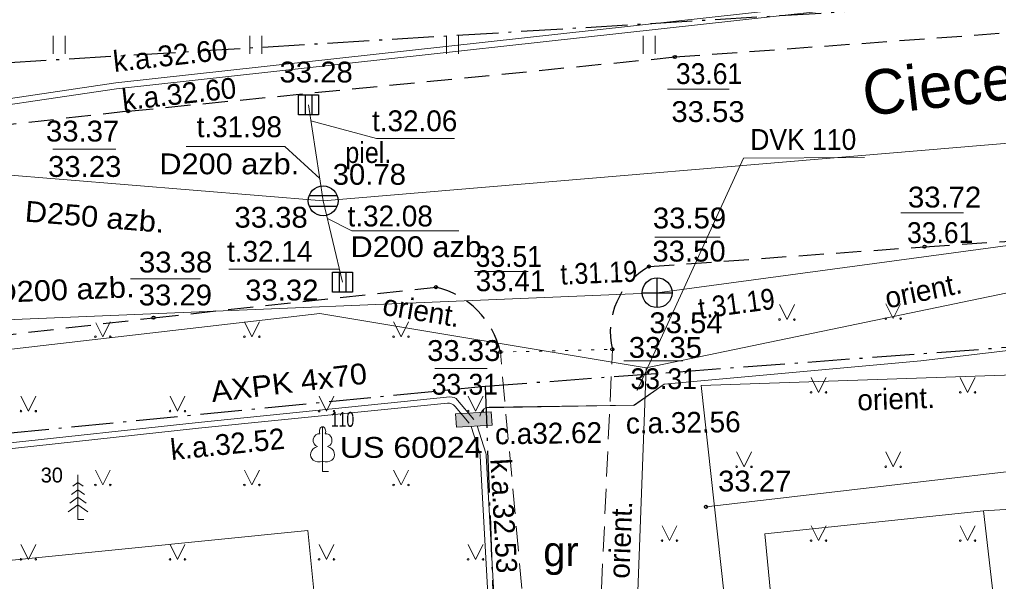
# Model space of a CAD drawing. Extents: x 380758 to 381729, y 283236 to 283533.
# Drawn here: x 381053.95 to 381086.8, y 283323.24 to 283342.11 of the extents above; entities that cross this region are included whole.
import ezdxf
from ezdxf.enums import TextEntityAlignment as Align

# ---------------------------------------------------------------- set-up
doc = ezdxf.new("R2010")
doc.units = 0
doc.header["$LTSCALE"] = 0.28
for name, pattern in [('DOT_DASHED', [7.7, 5, -1.2, 0.3, -1.2]), ('DOTTED', [1.5, 0.3, -1.2]), ('MEDIUM_DASHED', [4.5, 3, -1.5])]:
    doc.linetypes.add(name, pattern=pattern)
for name, color, linetype, lineweight in [('1', 7, 'Continuous', 13), ('11', 7, 'Continuous', 13), ('17', 7, 'Continuous', 13), ('18', 7, 'Continuous', 13), ('23', 7, 'Continuous', 13), ('29', 7, 'DOT_DASHED', 25), ('35', 7, 'Continuous', 13), ('37', 7, 'MEDIUM_DASHED', 13), ('38', 7, 'Continuous', 25), ('45', 7, 'Continuous', 13), ('47', 7, 'Continuous', 13), ('48', 7, 'Continuous', 25), ('58', 7, 'Continuous', 25), ('7', 7, 'Continuous', 13), ('9', 7, 'Continuous', 13)]:
    doc.layers.add(name, color=color, linetype=linetype, lineweight=lineweight)
doc.layers.add('56', color=7, linetype='Continuous')

msp = doc.modelspace()

# ---------------------------------------------------------------- hatches: boundary and pattern name
at = {"layer": '18'}
msp.add_hatch(color=256, dxfattribs=at).paths.add_polyline_path([(381068.581, 283328.865), (381069.779, 283328.94), (381069.807, 283328.491), (381068.609, 283328.416)])

# ---------------------------------------------------------------- linework, layer by layer
at = {"layer": '1'}
for p, q in [((381064.116, 283328.432), (381064.116, 283327.279)), ((381064.206, 283328.2), (381064.205, 283328.201)), ((381064.116, 283327.279), (381064.116, 283326.932)), ((381055.906, 283326.818), (381055.906, 283325.318)), ((381064.116, 283326.932), (381064.316, 283326.932)), ((381055.906, 283326.568), (381055.73, 283326.44)), ((381055.906, 283326.568), (381056.08, 283326.44)), ((381055.906, 283326.068), (381055.628, 283325.864)), ((381055.906, 283326.318), (381055.69, 283326.16)), ((381055.906, 283326.318), (381056.122, 283326.16)), ((381055.906, 283326.068), (381056.184, 283325.864)), ((381055.906, 283325.818), (381055.574, 283325.574)), ((381055.906, 283325.818), (381056.24, 283325.574)), ((381055.906, 283325.318), (381056.106, 283325.318))]:
    msp.add_line(p, q, dxfattribs=at)
msp.add_lwpolyline([(381076.989, 283325.745), (381094.84, 283327.827), (381097.154, 283316.912)], dxfattribs=at)
for centre, major_axis, ratio, start_param, end_param in [((381064.1164, 283328.2821), (0, -0.1499), 0.707107, 3.1453698, 5.2874846), ((381064.1156, 283328.2821), (0, -0.1499), 0.707107, 0.9957007, 3.1378155), ((381063.9877, 283327.9872), (-0.0387, -0.2124), 0.861323, 3.1415927, 6.2831853), ((381064.2443, 283327.9872), (0.0387, -0.2124), 0.861323, 6.2831853, 9.424778), ((381064.0264, 283327.5249), (0.3068, 0.0951), 0.814445, 1.5707963, 4.7520146), ((381064.2056, 283327.5249), (-0.3068, 0.0951), 0.814445, 1.5311707, 4.712389)]:
    msp.add_ellipse(centre, major_axis=major_axis, ratio=ratio, start_param=start_param, end_param=end_param, dxfattribs=at)
at = {"layer": '11'}
for p, q in [((381064.135, 283336.022), (381114.289, 283340.241)), ((381064.135, 283336.022), (381063.643, 283339.248)), ((381045.914, 283337.51), (381064.135, 283336.022)), ((381064.135, 283336.022), (381064.786, 283333.287)), ((381060.967, 283333.732), (381064.68, 283333.732))]:
    msp.add_line(p, q, dxfattribs=at)
for points in [[(381068.541, 283338.115), (381065.925, 283338.115), (381063.726, 283338.706)], [(381059.537, 283337.841), (381062.853, 283337.841), (381064.02, 283336.773)], [(381068.693, 283335.01), (381065.104, 283335.01), (381064.277, 283335.424)]]:
    msp.add_lwpolyline(points, dxfattribs=at)
at = {"layer": '17'}
for points in [[(381104.068, 283335.267), (381095.95, 283334.767), (381074.983, 283330.417), (381064.026, 283332.241)], [(381045.194, 283329.97), (381049.305, 283330.531), (381064.026, 283332.241)], [(381074.983, 283330.417), (381074.575, 283319.597), (381079.19, 283319.291), (381080.612, 283314.576)]]:
    msp.add_lwpolyline(points, dxfattribs=at)
at = {"layer": '18'}
msp.add_lwpolyline([(381068.581, 283328.865), (381069.779, 283328.94), (381069.807, 283328.491), (381068.609, 283328.416)], close=True, dxfattribs=at)
at = {"layer": '23'}
for p, q in [((381055.077, 283340.961), (381055.077, 283341.561)), ((381055.477, 283340.961), (381055.477, 283341.561)), ((381061.677, 283340.961), (381061.677, 283341.561)), ((381062.077, 283340.961), (381062.077, 283341.561)), ((381068.277, 283340.961), (381068.277, 283341.561)), ((381068.677, 283340.961), (381068.677, 283341.561)), ((381074.877, 283340.961), (381074.877, 283341.561)), ((381075.277, 283340.961), (381075.277, 283341.561))]:
    msp.add_line(p, q, dxfattribs=at)
for points in [[(381079.457, 283332.535), (381079.707, 283332.035), (381079.957, 283332.535)], [(381083.021, 283332.567), (381083.271, 283332.067), (381083.521, 283332.567)], [(381056.51, 283331.923), (381056.742, 283331.459), (381056.992, 283331.959)], [(381061.496, 283331.959), (381061.746, 283331.459), (381061.996, 283331.959)], [(381066.5, 283331.959), (381066.75, 283331.459), (381067, 283331.959)], [(381080.517, 283330.089), (381080.767, 283329.589), (381081.017, 283330.089)], [(381085.521, 283330.089), (381085.771, 283329.589), (381086.021, 283330.089)], [(381053.992, 283329.459), (381054.242, 283328.959), (381054.492, 283329.459)], [(381058.996, 283329.459), (381059.246, 283328.959), (381059.496, 283329.459)], [(381064, 283329.459), (381064.25, 283328.959), (381064.5, 283329.459)], [(381069.004, 283329.459), (381069.254, 283328.959), (381069.504, 283329.459)], [(381078.017, 283327.589), (381078.267, 283327.089), (381078.517, 283327.589)], [(381083.021, 283327.589), (381083.271, 283327.089), (381083.521, 283327.589)], [(381056.492, 283326.981), (381056.742, 283326.481), (381056.992, 283326.981)], [(381061.496, 283326.981), (381061.746, 283326.481), (381061.996, 283326.981)], [(381066.5, 283326.981), (381066.75, 283326.481), (381067, 283326.981)], [(381075.513, 283325.111), (381075.763, 283324.611), (381076.013, 283325.111)], [(381080.517, 283325.111), (381080.767, 283324.611), (381081.017, 283325.111)], [(381085.521, 283325.111), (381085.771, 283324.611), (381086.021, 283325.111)], [(381053.992, 283324.481), (381054.242, 283323.981), (381054.492, 283324.481)], [(381058.996, 283324.481), (381059.246, 283323.981), (381059.496, 283324.481)], [(381064, 283324.481), (381064.25, 283323.981), (381064.5, 283324.481)], [(381069.004, 283324.481), (381069.254, 283323.981), (381069.504, 283324.481)]]:
    msp.add_lwpolyline(points, dxfattribs=at)
for centre, radius in [((381079.4566, 283332.0342), 0.028), ((381079.9566, 283332.0342), 0.0263), ((381083.0206, 283332.0669), 0.028), ((381083.5206, 283332.0669), 0.0263), ((381056.4915, 283331.4581), 0.028), ((381056.9915, 283331.4581), 0.0263), ((381061.4955, 283331.4581), 0.028), ((381061.9955, 283331.4581), 0.0263), ((381066.4995, 283331.4581), 0.028), ((381066.9995, 283331.4581), 0.0263), ((381080.5166, 283329.5889), 0.028), ((381081.0166, 283329.5889), 0.0263), ((381085.5206, 283329.5889), 0.028), ((381086.0206, 283329.5889), 0.0263), ((381053.9915, 283328.9581), 0.028), ((381054.4915, 283328.9581), 0.0263), ((381058.9955, 283328.9581), 0.028), ((381059.4955, 283328.9581), 0.0263), ((381063.9995, 283328.9581), 0.028), ((381064.4995, 283328.9581), 0.0263), ((381069.0035, 283328.9581), 0.028), ((381069.5035, 283328.9581), 0.0263), ((381078.0166, 283327.0889), 0.028), ((381078.5166, 283327.0889), 0.0263), ((381083.0206, 283327.0889), 0.028), ((381083.5206, 283327.0889), 0.0263), ((381056.4915, 283326.4801), 0.028), ((381056.9915, 283326.4801), 0.0263), ((381061.4955, 283326.4801), 0.028), ((381061.9955, 283326.4801), 0.0263), ((381066.4995, 283326.4801), 0.028), ((381066.9995, 283326.4801), 0.0263), ((381075.5126, 283324.6109), 0.028), ((381076.0126, 283324.6109), 0.0263), ((381080.5166, 283324.6109), 0.028), ((381081.0166, 283324.6109), 0.0263), ((381085.5206, 283324.6109), 0.028), ((381086.0206, 283324.6109), 0.0263), ((381053.9915, 283323.9801), 0.028), ((381054.4915, 283323.9801), 0.0263), ((381058.9955, 283323.9801), 0.028), ((381059.4955, 283323.9801), 0.0263), ((381063.9995, 283323.9801), 0.028), ((381064.4995, 283323.9801), 0.0263), ((381069.0035, 283323.9801), 0.028), ((381069.5035, 283323.9801), 0.0263)]:
    msp.add_circle(centre, radius, dxfattribs=at)
at = {"layer": '29'}
for p, q in [((381234.784, 283351.686), (381044.752, 283340.119)), ((381069.578, 283329.798), (381101.88, 283332.21)), ((381029.754, 283325.877), (381069.578, 283329.798)), ((381069.578, 283329.798), (381070.558, 283303.137))]:
    msp.add_line(p, q, dxfattribs=at)
at = {"layer": '35'}
msp.add_line((381086.298, 283325.608), (381087.497, 283315.497), dxfattribs=at)
for points in [[(381079.756, 283316.594), (381078.967, 283324.84), (381086.298, 283325.608), (381094.353, 283326.102)], [(381064.622, 283314.991), (381063.627, 283324.947), (381047.892, 283323.375)]]:
    msp.add_lwpolyline(points, dxfattribs=at)
at = {"layer": '37', "lineweight": 25}
for p, q in [((381057.591, 283339.033), (381048.558, 283338.001)), ((381058.443, 283332.096), (381067.925, 283333.123))]:
    msp.add_line(p, q, dxfattribs=at)
at = {"layer": '37', "linetype": 'DOTTED'}
msp.add_line((381070.084, 283330.944), (381073.845, 283331.033), dxfattribs=at)
at = {"layer": '37', "lineweight": 25}
for points in [[(381057.591, 283339.033), (381075.94, 283340.852), (381097.005, 283342.39), (381119.536, 283343.592), (381136.671, 283344.454), (381156.115, 283345.485), (381163.151, 283345.848), (381179.391, 283346.671), (381179.402, 283346.957), (381180.543, 283347.053), (381180.574, 283346.748), (381189.023, 283347.214), (381204.943, 283348.182)], [(381075.076, 283333.816), (381084.324, 283334.48), (381096.989, 283335.317)], [(381045.126, 283330.465), (381049.242, 283331.027), (381058.443, 283332.096)]]:
    msp.add_lwpolyline(points, dxfattribs=at)
at = {"layer": '37'}
for points in [[(381072.952, 283311.831), (381073.424, 283321.729), (381073.845, 283331.033)], [(381070.772, 283318.602), (381070.922, 283321.749), (381070.084, 283330.944)]]:
    msp.add_lwpolyline(points, dxfattribs=at)
at = {"layer": '37', "lineweight": 25}
for centre, radius, start, end in [((381076.2854, 283331.6173), 2.5093, 118.8123, 193.46536), ((381067.2538, 283330.2989), 2.9028, 12.84095, 76.63074)]:
    msp.add_arc(centre, radius, start, end, dxfattribs=at)
at = {"layer": '38'}
for p, q in [((381075.347, 283332.437), (381075.347, 283333.437)), ((381074.847, 283332.937), (381075.847, 283332.937))]:
    msp.add_line(p, q, dxfattribs=at)
msp.add_circle((381075.347, 283332.937), 0.5, dxfattribs=at)
at = {"layer": '45'}
msp.add_lwpolyline([(381032.402, 283337.854), (381049.394, 283338.981), (381050.924, 283339.056), (381057.172, 283339.986), (381081.97, 283342.714), (381090.848, 283343.32), (381093.46, 283343.399), (381097.843, 283343.028)], dxfattribs=at)
at = {"layer": '47'}
for p, q in [((381075.347, 283332.937), (381126.982, 283339.91)), ((381043.031, 283331.59), (381075.347, 283332.937))]:
    msp.add_line(p, q, dxfattribs=at)
at = {"layer": '48'}
for p, q in [((381063.53, 283339.586), (381063.53, 283338.911)), ((381063.755, 283339.586), (381063.755, 283338.911)), ((381063.667, 283336.197), (381064.603, 283336.197)), ((381063.667, 283335.847), (381064.603, 283335.847)), ((381064.673, 283333.625), (381064.673, 283332.95)), ((381064.898, 283333.625), (381064.898, 283332.95))]:
    msp.add_line(p, q, dxfattribs=at)
for points in [[(381063.305, 283339.586), (381063.98, 283339.586), (381063.98, 283338.911), (381063.305, 283338.911)], [(381064.448, 283333.625), (381065.123, 283333.625), (381065.123, 283332.95), (381064.448, 283332.95)]]:
    msp.add_lwpolyline(points, close=True, dxfattribs=at)
msp.add_circle((381064.135, 283336.022), 0.5, dxfattribs=at)
at = {"layer": '58', "lineweight": 13}
for p, q in [((381075.691, 283339.775), (381077.77, 283339.775)), ((381055.058, 283337.761), (381057.181, 283337.761)), ((381083.53, 283335.615), (381085.631, 283335.615)), ((381075.268, 283334.802), (381077.459, 283334.802)), ((381069.212, 283333.651), (381071.019, 283333.651)), ((381057.674, 283333.4), (381060.023, 283333.4)), ((381074.227, 283330.644), (381076.215, 283330.644)), ((381067.881, 283330.394), (381069.643, 283330.394))]:
    msp.add_line(p, q, dxfattribs=at)
at = {"layer": '58'}
for centre in [(381075.94, 283340.8521), (381057.591, 283339.0331), (381084.324, 283334.4801), (381075.076, 283333.8161), (381067.925, 283333.1231), (381058.443, 283332.0961), (381070.084, 283330.9441), (381073.845, 283331.0331), (381076.989, 283325.7451)]:
    msp.add_circle(centre, 0.0534, dxfattribs=at)
at = {"layer": '7'}
for p, q in [((381074.558, 283329.149), (381075.586, 283329.862)), ((381069.194, 283328.678), (381068.651, 283329.329)), ((381068.565, 283329.119), (381069.04, 283328.55)), ((381069.574, 283329.07), (381074.576, 283329.157)), ((381069.4, 283328.791), (381069.434, 283328.892)), ((381069.108, 283328.447), (381069.397, 283327.532)), ((381069.308, 283328.46), (381069.596, 283327.543))]:
    msp.add_line(p, q, dxfattribs=at)
for points in [[(381050.816, 283338.838), (381057.197, 283339.787), (381081.988, 283342.515), (381090.847, 283343.119), (381098.274, 283342.489), (381113.806, 283343.268)], [(381074.679, 283329.653), (381078.243, 283337.457), (381082.304, 283337.475)], [(381069.714, 283329.095), (381074.582, 283329.163), (381075.583, 283329.866), (381084.199, 283330.643), (381097.81, 283332.257), (381102.319, 283332.897)], [(381068.391, 283329.435), (381059.936, 283328.582), (381053.331, 283327.865)], [(381045.932, 283326.569), (381053.08, 283327.636), (381059.957, 283328.383), (381068.305, 283329.225)], [(381069.41, 283327.458), (381070.001, 283316.756), (381070.197, 283315.281), (381069.382, 283312.709), (381068.419, 283311.566), (381067.557, 283310.97), (381067.026, 283310.556)], [(381069.61, 283327.469), (381070.2, 283316.775), (381070.401, 283315.263), (381071.189, 283312.035)]]:
    msp.add_lwpolyline(points, dxfattribs=at)
for centre, start, end in [((381068.4207, 283329.1365), 39.842, 95.7613), ((381068.3351, 283328.9269), 39.84201, 95.7613), ((381069.7183, 283328.7952), 90.79869, 161.21987), ((381069.1105, 283327.4418), 3.16033, 17.49679), ((381069.3102, 283327.4529), 3.16033, 17.47759)]:
    msp.add_arc(centre, 0.3, start, end, dxfattribs=at)
at = {"layer": '9'}
msp.add_lwpolyline([(381078.149, 283317.798), (381076.827, 283329.819), (381117.557, 283331.209), (381143.607, 283331.542), (381159.963, 283331.675), (381160.55, 283326.135), (381161.093, 283317.037)], dxfattribs=at)

# ---------------------------------------------------------------- texts
at = {"layer": '1', "width": 0.7}
msp.add_text('110', height=0.5, dxfattribs=at).set_placement((381064.396, 283328.432))
at = {"layer": '1'}
msp.add_text('30', height=0.5, dxfattribs=at).set_placement((381054.656, 283326.562))
at = {"layer": '11'}
for s, p in [('t.31.98', (381061.321, 283338.159)), ('t.32.06', (381067.209, 283338.359)), ('t.32.08', (381066.3865, 283335.162)), ('t.32.14', (381062.3415, 283333.975))]:
    msp.add_text(s, height=0.7, dxfattribs=at).set_placement(p, align=Align.CENTER)
at = {"layer": '11', "width": 1.1}
for p in [(381060.986, 283336.913), (381067.402, 283334.131)]:
    msp.add_text('D200 azb.', height=0.7, dxfattribs=at).set_placement(p, align=Align.CENTER)
msp.add_text('D250 azb.', height=0.7, rotation=355.331, dxfattribs=at).set_placement((381056.442, 283335.1382), align=Align.CENTER)
at = {"layer": '17'}
for rotation, p in [(11.719, (381084.3519, 283332.6676)), (350.551, (381067.379, 283331.9873)), (87.841, (381074.4647, 283324.6243))]:
    msp.add_text('orient.', height=0.7, rotation=rotation, dxfattribs=at).set_placement(p, align=Align.CENTER)
at = {"layer": '37'}
msp.add_text('gr', height=1, dxfattribs=at).set_placement((381072.12, 283323.753), align=Align.CENTER)
at = {"layer": '38', "width": 1.05}
msp.add_text('33.54', height=0.7, dxfattribs=at).set_placement((381075.088, 283331.577))
at = {"layer": '45'}
msp.add_text('k.a.32.60', height=0.7, rotation=6.277, dxfattribs=at).set_placement((381057.125, 283340.349))
at = {"layer": '47'}
for s, rotation, width, p in [('t.31.19', 2.387, 0.9, (381073.4019, 283333.2587)), ('D200 azb.', 2.387, 1.1, (381055.4684, 283332.6897)), ('t.31.19', 7.691, 0.9, (381078.0577, 283332.228))]:
    msp.add_text(s, height=0.7, rotation=rotation, dxfattribs=dict(at, width=width)).set_placement(p, align=Align.CENTER)
at = {"layer": '48', "width": 1.05}
for s, p in [('33.28', (381062.671, 283339.997)), ('33.38', (381061.159, 283335.12)), ('33.32', (381061.519, 283332.674))]:
    msp.add_text(s, height=0.7, dxfattribs=at).set_placement(p)
at = {"layer": '48'}
for s, width, p in [('piel.', 0.9, (381065.6525, 283337.293)), ('30.78', 1.05, (381065.6865, 283336.561))]:
    msp.add_text(s, height=0.7, dxfattribs=dict(at, width=width)).set_placement(p, align=Align.CENTER)
at = {"layer": '56'}
msp.add_text('Cieceres iela', height=1.5, rotation=6.627, dxfattribs=at).set_placement((381082.333, 283338.865))
at = {"layer": '58'}
for s, width, p in [('33.61', 0.95, (381075.978, 283339.943)), ('33.53', 1.05, (381075.826, 283338.669)), ('33.37', 1.05, (381054.832, 283338.014)), ('33.23', 1.05, (381054.903, 283336.825)), ('33.72', 1.05, (381083.767, 283335.797)), ('33.59', 1.05, (381075.204, 283335.095)), ('33.61', 0.95, (381083.736, 283334.604)), ('33.50', 1.05, (381075.188, 283333.982)), ('33.38', 1.05, (381057.953, 283333.614)), ('33.51', 0.95, (381069.255, 283333.803)), ('33.29', 1.05, (381057.945, 283332.509)), ('33.33', 1.05, (381067.627, 283330.644)), ('33.35', 1.05, (381074.396, 283330.749)), ('33.31', 0.95, (381074.454, 283329.698)), ('33.31', 0.95, (381067.779, 283329.512)), ('33.27', 1.05, (381077.393, 283326.26))]:
    msp.add_text(s, height=0.7, dxfattribs=dict(at, width=width)).set_placement(p)
msp.add_text('33.41', height=0.7, dxfattribs=at).set_placement((381069.256, 283332.987))
at = {"layer": '7'}
for s, rotation, p in [('k.a.32.60', 6.277, (381057.422, 283339.055)), ('c.a.32.56', 0.799, (381074.303, 283328.202)), ('k.a.32.52', 5.761, (381059.044, 283327.313)), ('c.a32.62', 0.799, (381069.911, 283327.843)), ('k.a.32.53', 273.16, (381069.747, 283327.346))]:
    msp.add_text(s, height=0.7, rotation=rotation, dxfattribs=at).set_placement(p)
for s, width, p in [('DVK 110', 0.95, (381078.473, 283337.732)), ('US 60024', 1.15, (381064.698, 283327.391))]:
    msp.add_text(s, height=0.7, dxfattribs=dict(at, width=width)).set_placement(p)
at = {"layer": '7', "width": 1.1}
msp.add_text('AXPK 4x70', height=0.7, rotation=6.878, dxfattribs=at).set_placement((381060.415, 283329.26))
at = {"layer": '9'}
msp.add_text('orient.', height=0.7, rotation=1.955, dxfattribs=at).set_placement((381083.3791, 283329.0246), align=Align.CENTER)

doc.saveas('drawing.dxf')
